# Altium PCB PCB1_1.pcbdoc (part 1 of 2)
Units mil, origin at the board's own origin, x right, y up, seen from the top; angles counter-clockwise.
Board outline 2550 x 2850 mil, 4 copper layers (Top Layer, GND02, PWR03, Bottom Layer), stack 64.1 mil thick; 130 components, 80 nets, 440 pads, 327 vias.
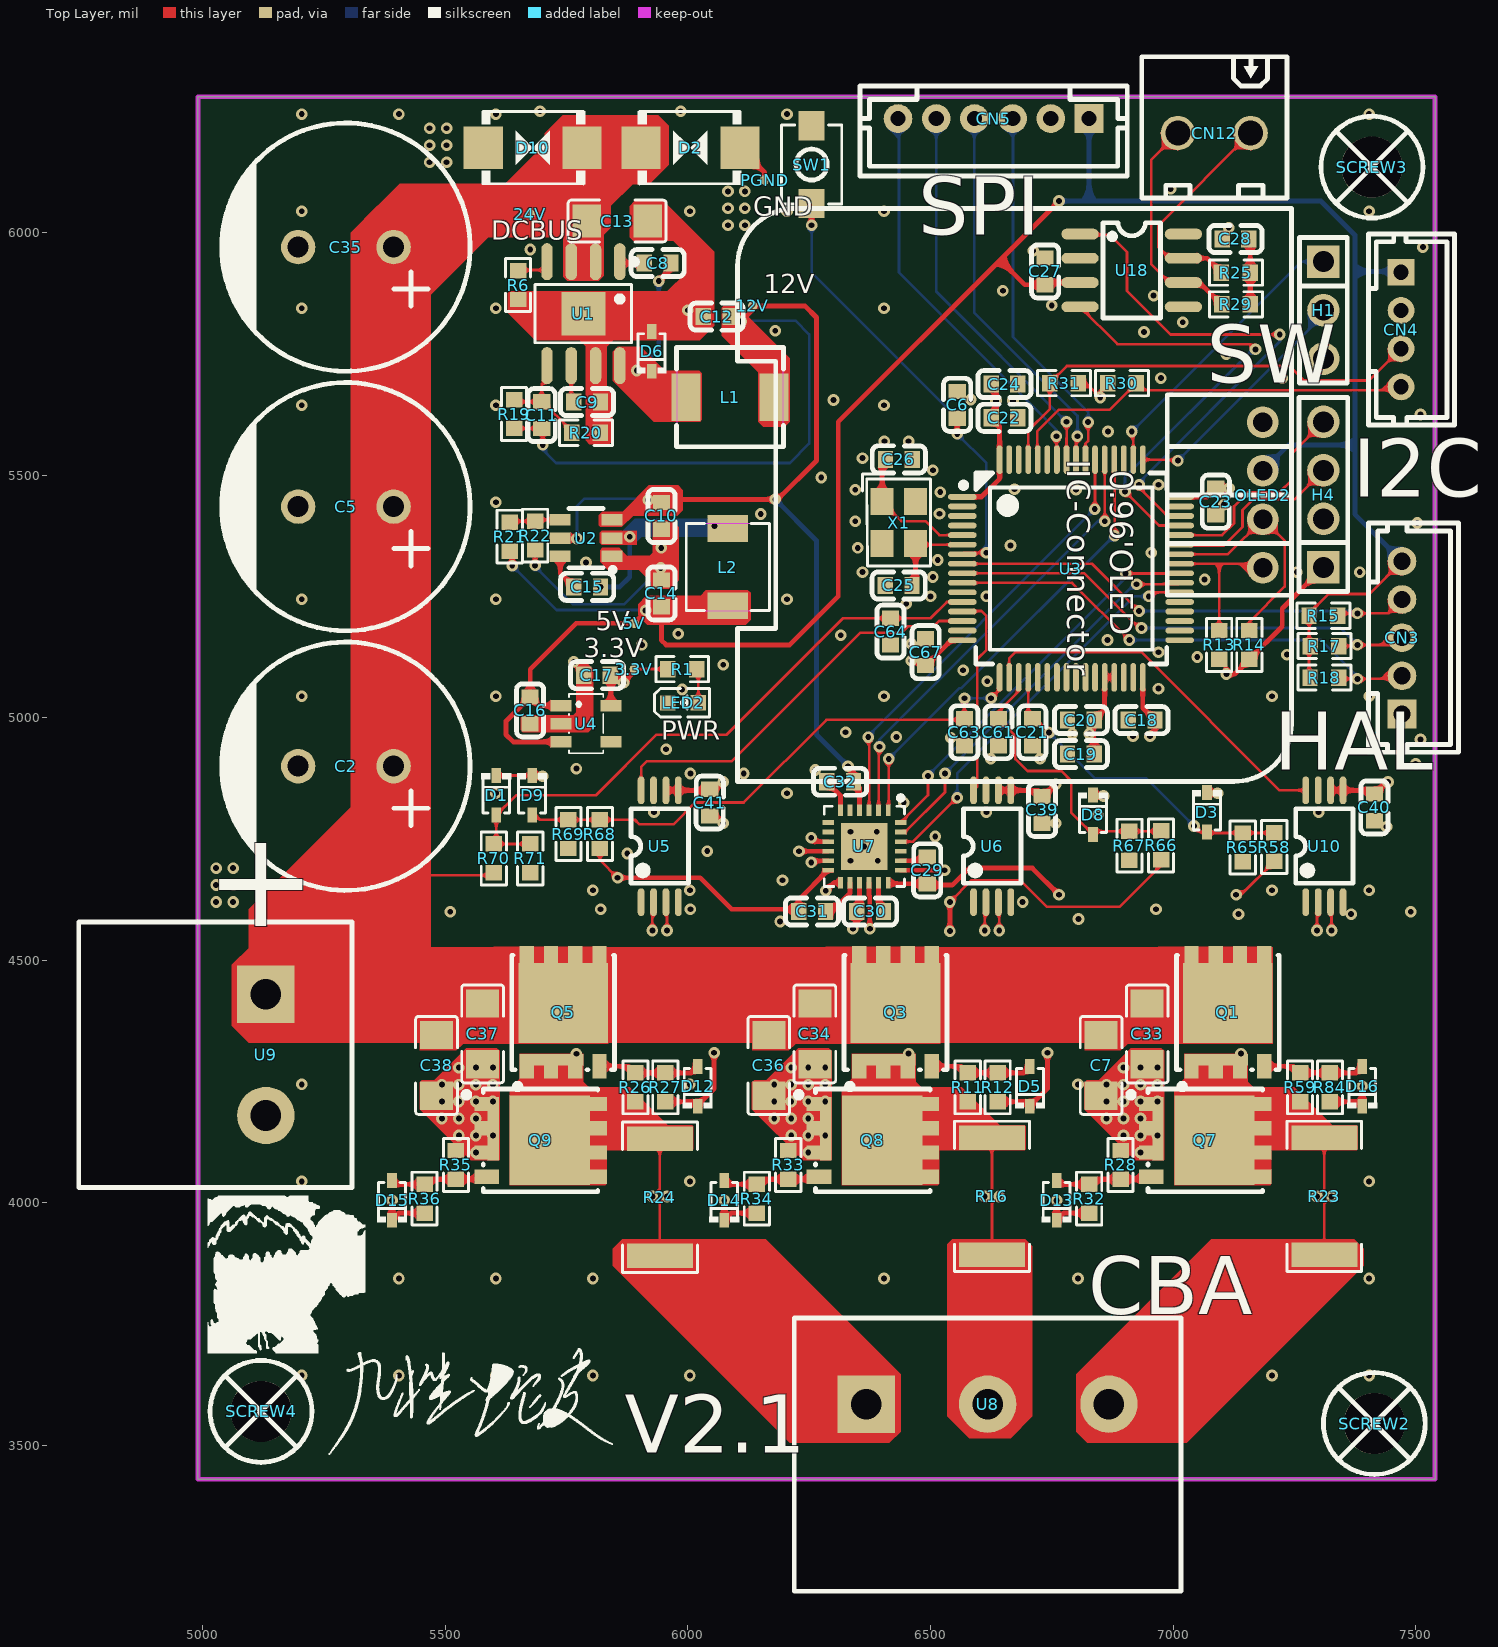
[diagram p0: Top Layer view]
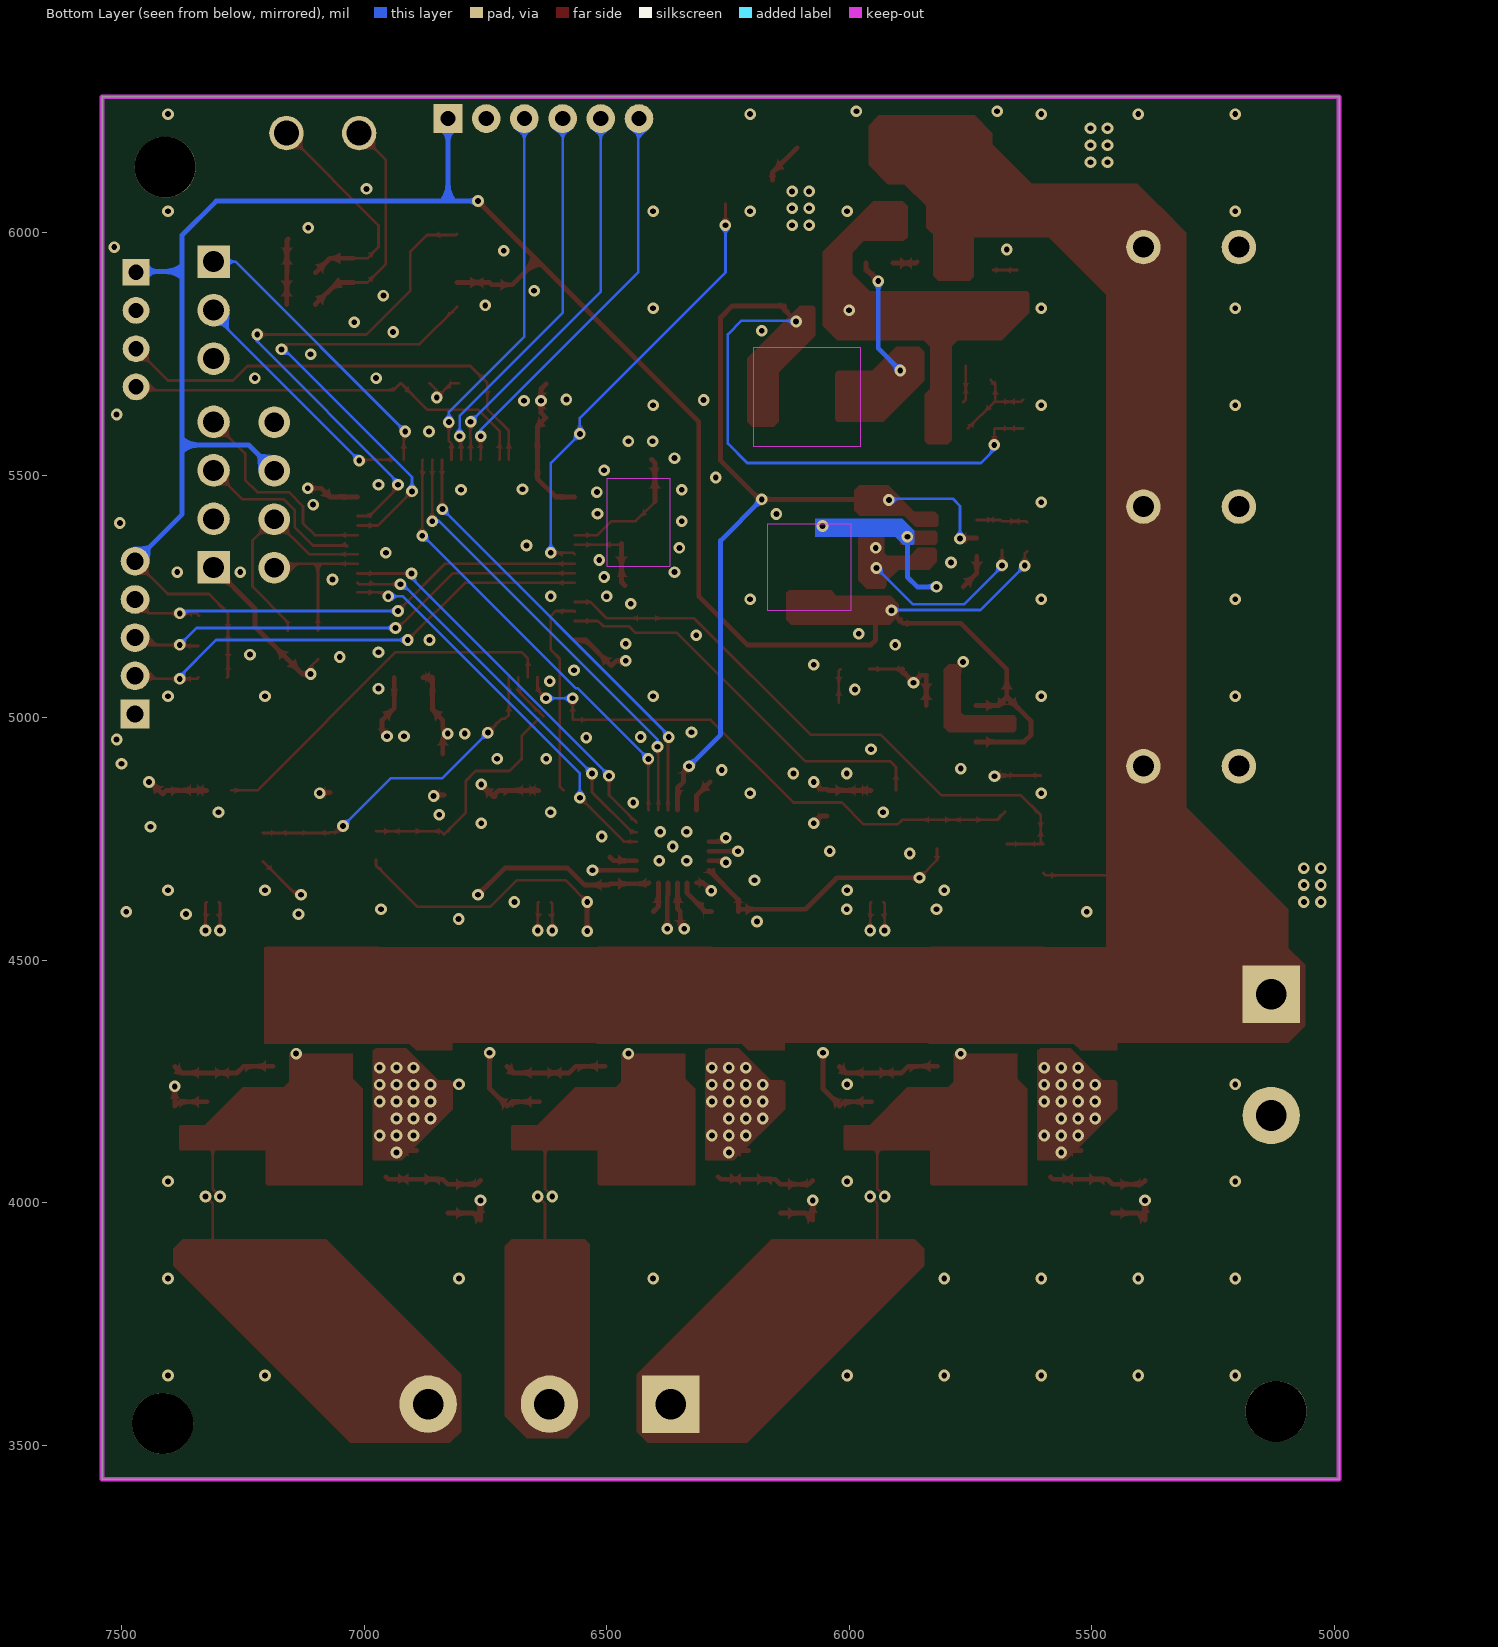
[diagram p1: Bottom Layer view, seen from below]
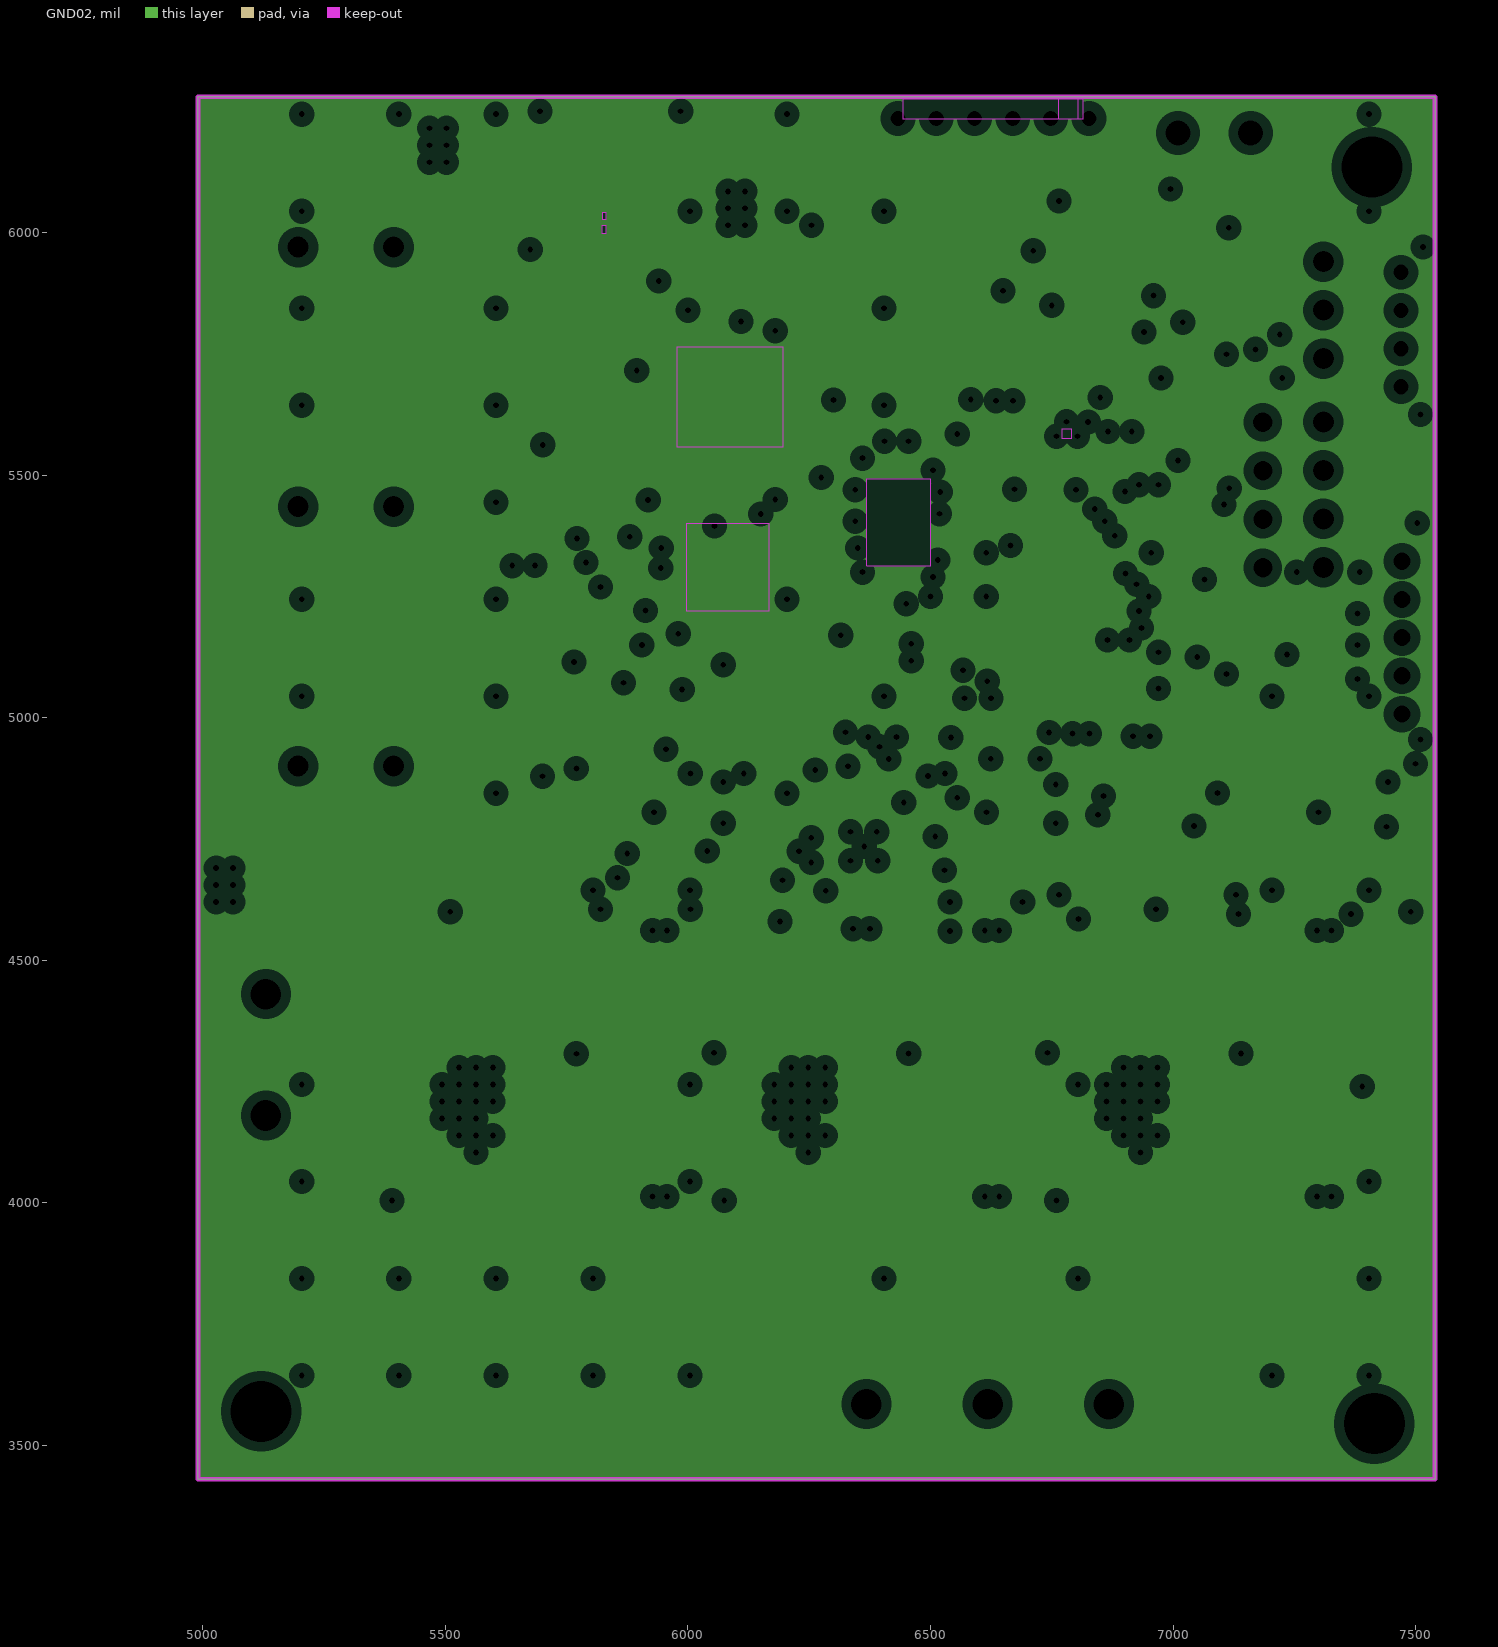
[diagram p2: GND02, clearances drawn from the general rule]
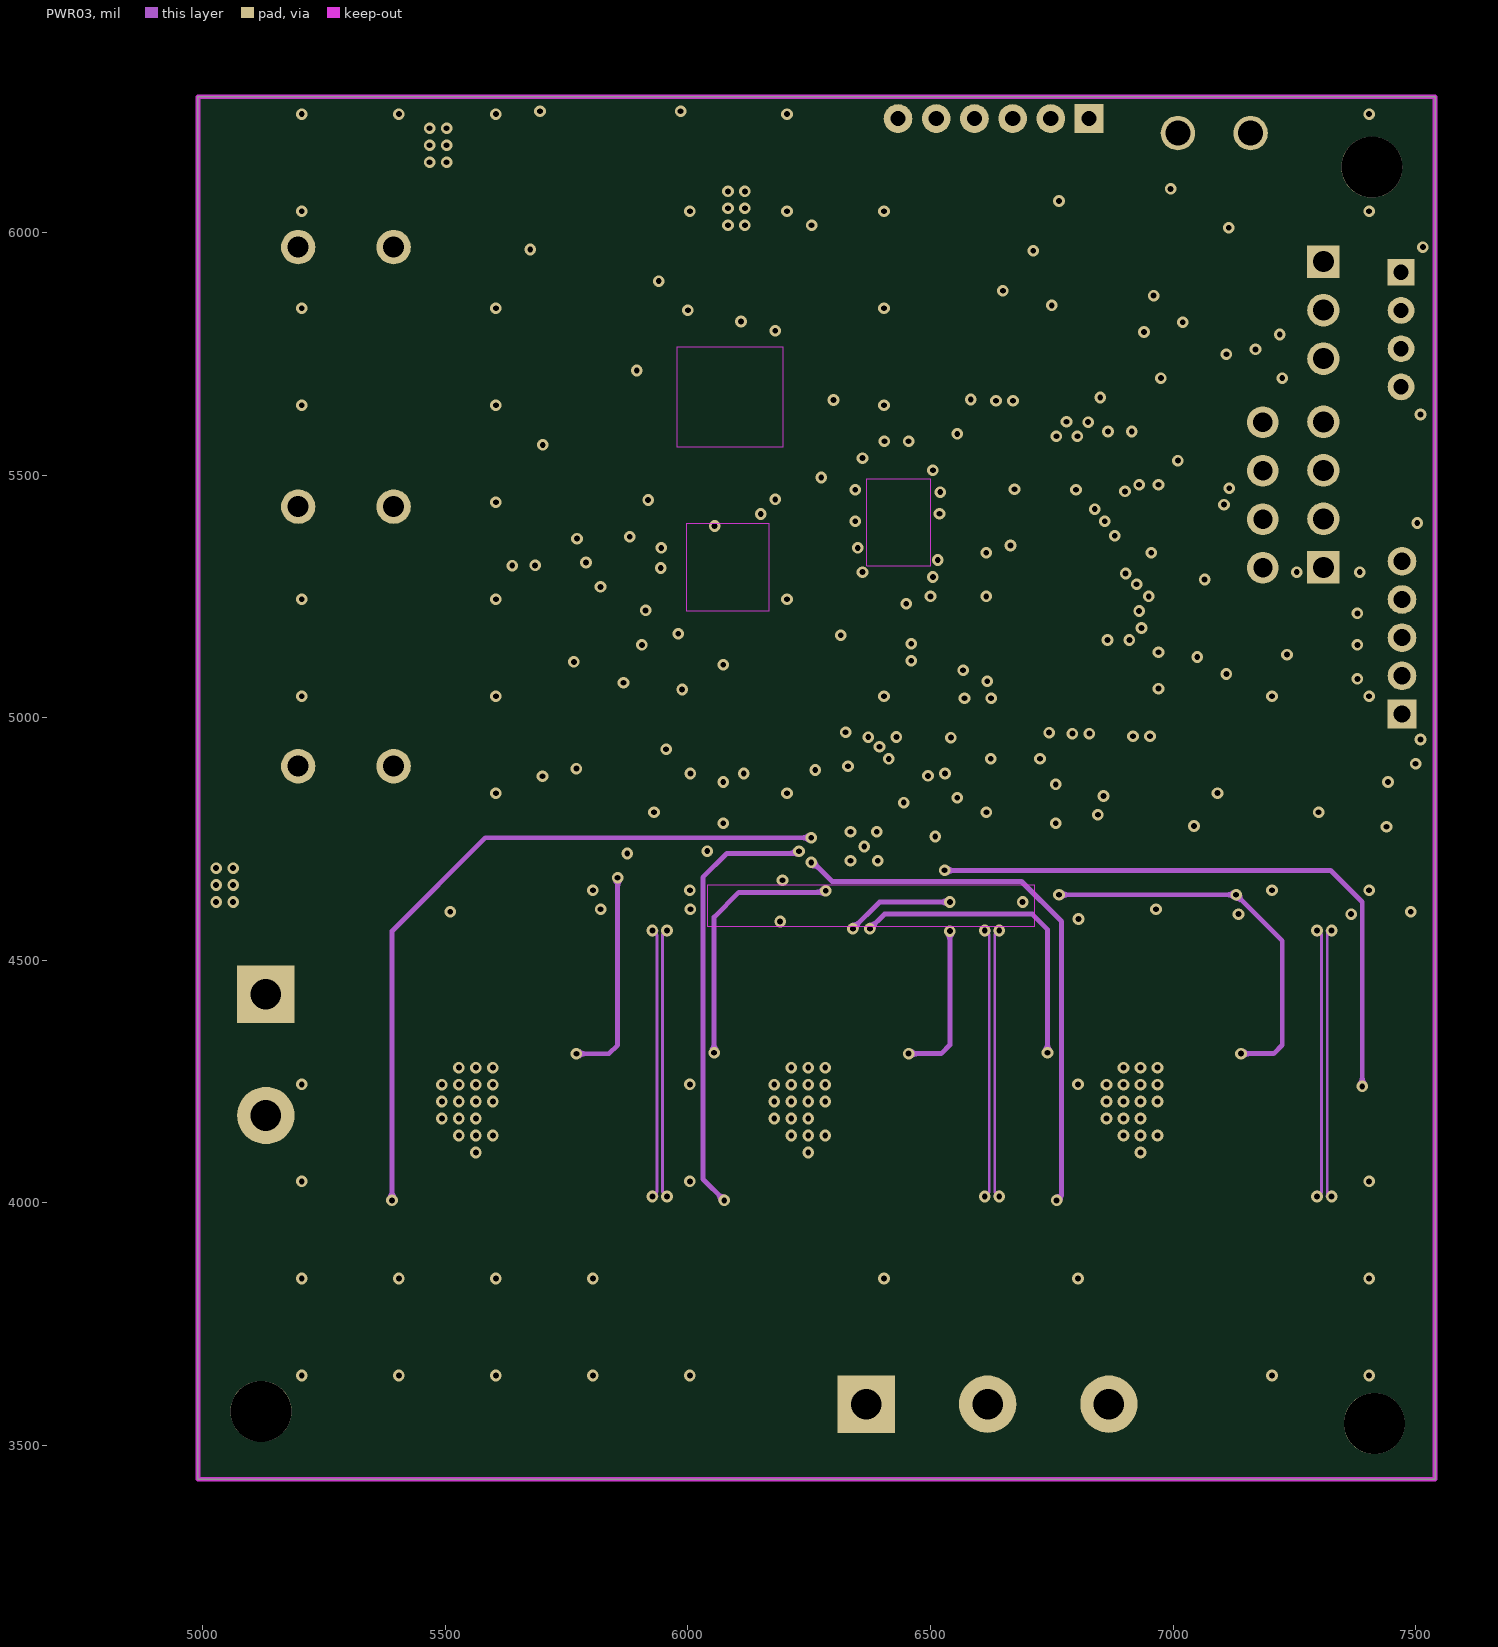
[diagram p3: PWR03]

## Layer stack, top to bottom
Top Layer: signal copper 1.4
Dielectric1: surface 8.3, 7628 RC49% 8.6mil, Dk 0
GND02: plane copper 1.4
Dielectric2: surface 41.9, 1.1mm H/HOZ Copper, Dk 0
PWR03: signal copper 1.4
Dielectric3: surface 8.3, 7628 RC49% 8.6mil, Dk 0
Bottom Layer: signal copper 1.4

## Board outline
4990,6280 4990,3430 7540,3430 7540,6280

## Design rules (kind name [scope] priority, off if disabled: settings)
BoardOutlineClearance copperThickness1oz [All] p0: genericclearance=10 ignorepadtopadclearanceinfootprint=FALSE except(0: Arc-SplitContinuation Track-SplitContinuation SMDPad-SplitContinuation THPad-SplitContinuation Via-SplitContinuation Fill-SplitContinuation Poly-SplitContinuation Region-SplitContinuation Text-SplitContinuation)
BoardOutlineClearance copperThickness2oz [All] p0: genericclearance=10 ignorepadtopadclearanceinfootprint=FALSE except(0: Arc-SplitContinuation Track-SplitContinuation SMDPad-SplitContinuation THPad-SplitContinuation Via-SplitContinuation Fill-SplitContinuation Poly-SplitContinuation Region-SplitContinuation Text-SplitContinuation)
BoardOutlineClearance copperThicknessInner0.5oz [All] p0: genericclearance=10 ignorepadtopadclearanceinfootprint=FALSE except(0: Arc-SplitContinuation Track-SplitContinuation SMDPad-SplitContinuation THPad-SplitContinuation Via-SplitContinuation Fill-SplitContinuation Poly-SplitContinuation Region-SplitContinuation Text-SplitContinuation)
BoardOutlineClearance 3W [All] p0: genericclearance=10 ignorepadtopadclearanceinfootprint=FALSE except(0: Arc-SplitContinuation Track-SplitContinuation SMDPad-SplitContinuation THPad-SplitContinuation Via-SplitContinuation Fill-SplitContinuation Poly-SplitContinuation Region-SplitContinuation Text-SplitContinuation)
BoardOutlineClearance otherClearance [All] p0: genericclearance=10 ignorepadtopadclearanceinfootprint=FALSE except(0: Arc-SplitContinuation Track-SplitContinuation SMDPad-SplitContinuation THPad-SplitContinuation Via-SplitContinuation Fill-SplitContinuation Poly-SplitContinuation Region-SplitContinuation Text-SplitContinuation)
Clearance copperThickness1oz [All] p1: gap=7 ignorepadtopadclearanceinfootprint=FALSE
Clearance copperThickness2oz [All] p1: gap=7 ignorepadtopadclearanceinfootprint=FALSE
Clearance copperThicknessInner0.5oz [All] p1: gap=7 ignorepadtopadclearanceinfootprint=FALSE
Clearance 3W [(InNet('PF1-OSC_OUT') OR InNet('PF0-OSC_IN') OR InNet('ADC_AI') OR InNet('ADC_BI') OR InNet('ADC_CI') OR InNet('ADC_AU') OR InNet('ADC_BU') OR InNet('ADC_CU'))] p1: gap=7 ignorepadtopadclearanceinfootprint=FALSE
Clearance otherClearance [All] p1: gap=7 ignorepadtopadclearanceinfootprint=FALSE
DiffPairsRouting differentialPair [All] p1: maxuncoupledlength=10 minlimit=5.9843 maxlimit=Infinity mostfreqgap=5.9843 toplayer_minwidth=5 toplayer_prefwidth=10 toplayer_maxwidth=100 bottomlayer_minwidth=5 bottomlayer_prefwidth=10 bottomlayer_maxwidth=100 midlayer1_minwidth=5 midlayer1_prefwidth=10 midlayer1_maxwidth=100
PasteMaskExpansion pasteMaskExpansion [All] p1: expansion=0
PlaneConnect innerPlane [All] p1: planeconnectstyle=Relief reliefexpansion=20 reliefentries=4 reliefconductorwidth=10 reliefairgap=10
PlaneConnect 直连 [All] p1: planeconnectstyle=Direct reliefexpansion=20 reliefentries=4 reliefconductorwidth=10 reliefairgap=10
PolygonConnect copperRegion [All] p1: connectstyle=Relief reliefentries=4 reliefconductorwidth=10 polygonreliefangle="90 Angle" airgapwidth=10
PolygonConnect 直连 [All] p1: connectstyle=Direct reliefentries=4 reliefconductorwidth=10 polygonreliefangle="90 Angle" airgapwidth=10
RoutingVias viaSize [All] p1: viastyle="Through Hole" holewidth=12 minholewidth=7.874 maxholewidth=248.0314 width=12 minwidth=7.874 maxwidth=248.0314
RoutingVias 大过孔 [All] p1: viastyle="Through Hole" holewidth=12.0078 minholewidth=11.811 maxholewidth=248.0316 width=12.0078 minwidth=11.811 maxwidth=248.0316
SolderMaskExpansion solderMaskExpansion [IsVia] p1: useseparateexpansions=TRUE expansion=-1000 expansionbottom=-1000
SolderMaskExpansion solderMaskExpansion [All] p2: useseparateexpansions=TRUE expansion=2.0079 expansionbottom=2.0079
Width copperThickness1oz [All] p1: maxlimit=100 minlimit=4 preferedwidth=6
Width copperThickness2oz [All] p1: maxlimit=100 minlimit=8 preferedwidth=10
Width copperThickness0.5oz [All] p1: maxlimit=100 minlimit=4 preferedwidth=10

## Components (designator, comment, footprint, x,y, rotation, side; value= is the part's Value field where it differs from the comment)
3.3V "" Test-Point-0.5mm 5889.7,5100.2 r0 top
5V "" Test-Point-0.5mm 5889.1,5194.6 r0 top
12V "" Test-Point-0.5mm 6133.5,5849 r0 top
24V "" Test-Point-0.5mm 5674.7,6038.2 r0 top
C2 "470uF" CAP-TH_BD13.0-P5.00-D0.6-FD 5295,4900 r180 top
C5 "470uF" CAP-TH_BD13.0-P5.00-D0.6-FD 5295,5435 r180 top
C6 "100nF" C0603#1 6555,5645 r270 top
C7 "4.7uF" C1206 6851.8,4283.1 r270 top
C8 "100nF" C0603#2 5937.6,5937 r0 top
C9 "100nF" C0603#2 5792.1,5650.6 r180 top
C10 "100nF" C0603#1 5945.5,5415.8 r90 top
C11 "100nF" C0603#2 5698.5,5623.7 r270 top
C12 "100nF" C0603#2 6059.3,5826.8 r0 top
C13 "100nF" C1206 5854.1,6023.8 r180 top
C14 "100nF" C0603#3 5945.3,5256.2 r270 top
C15 "100nF" C0603#2 5792.2,5269.6 r0 top
C16 "100nF" C0603#3 5674.6,5015.1 r90 top
C17 "100nF" C0603#3 5812.6,5087.6 r0 top
C18 "100nF" C0603#1 6935,4995 r180 top
C19 "100nF" C0603#1 6810,4925 r180 top
C20 "100nF" C0603#1 6810,4995 r0 top
C21 "100nF" C0603#1 6710,4970 r90 top
C22 "100nF" C0603#2 6652.6,5618.2 r180 top
C23 "100nF" C0603#3 7088.1,5445.4 r90 top
C24 "100nF" C0603#2 6652.6,5687.7 r180 top
C25 "100nF" C0603#2 6434.5,5272.5 r0 top
C26 "100nF" C0603#3 6434.8,5532.5 r0 top
C27 "100nF" C0603#2 6736.3,5920 r270 top
C28 "100nF" C0603#3 7128.8,5986.8 r0 top
C29 "100nF" C0603#2 6493.3,4685.3 r90 top
C30 "100nF" C0603#2 6375.7,4600.5 r180 top
C31 "100nF" C0603#2 6255.9,4600.5 r180 top
C32 "100nF" C0603#2 6313.7,4868 r0 top
C33 "4.7uF" C1206 6946.8,4348.1 r270 top
C34 "4.7uF" C1206 6261.8,4348.1 r270 top
C35 "470uF" CAP-TH_BD13.0-P5.00-D0.6-FD 5295,5970 r180 top
C36 "4.7uF" C1206 6166.8,4283.1 r270 top
C37 "4.7uF" C1206 5576.8,4348.1 r270 top
C38 "4.7uF" C1206 5481.8,4283.1 r270 top
C39 "100nF" C0603#1 6730,4810 r90 top
C40 "100nF" C0603#1 7415,4815 r90 top
C41 "100nF" C0603#1 6045,4825 r90 top
C61 "100nF" C0603#1 6640,4970 r90 top
C63 "100nF" C0603#1 6570,4970 r90 top
C64 "100nF" C0603#2 6417.6,5177.4 r90 top
C67 "100nF" C0603#1 6490,5135 r270 top
CN3 "LAIL-PHC2.0-5P-01-PH-L" CONN-TH_5P-P2.00_ZX-PH2.0-5PZZ 7472,5165 r90 top
CN4 "LAIL-PHC2.0-4P-01-PH-L" CONN-TH_HC-PH-4A-Y-K-10 7470,5800 r270 top
CN5 "LAIL-PHC2.0-6P-01-PH-L" CONN-TH_6P-P2.00_LAIL-PHC2.0-6P-01-PH-L 6630,6235 r180 top
CN12 "MX128L-3.81-02P-GN01-Cu-Y-A" CONN-TH_2P-P3.81_MX128L-3.81-GN01-02P-CU-Y-A 7085,6205 r180 top
D1 "B16WS" SOD-323_L1.7-W1.3-LS2.5-FD#1 5605,4840 r90 top
D2 "SMBJ28CA" SMB_L4.6-W3.6-LS5.4-BI 6005,6175 r180 top
D3 "B16WS" SOD-323_L1.7-W1.3-LS2.5-FD#1 7070,4805 r90 top
D5 "B16WS" SOD-323_L1.7-W1.3-LS2.5-FD#1 6705,4240 r270 top
D6 "B16WS" SOD-323_L1.7-W1.3-LS2.5-FD#1 5925,5755 r270 top
D8 "B16WS" SOD-323_L1.7-W1.3-LS2.5-FD#1 6835,4800 r90 top
D9 "B16WS" SOD-323_L1.7-W1.3-LS2.5-FD#2 5678.7,4840 r90 top
D10 "SMBJ28CA" SMB_L4.6-W3.6-LS5.4-BI 5680,6175 r0 top
D12 "B16WS" SOD-323_L1.7-W1.3-LS2.5-FD#1 6020,4240 r270 top
D13 "B16WS" SOD-323_L1.7-W1.3-LS2.5-FD#1 6760,4005 r270 top
D14 "B16WS" SOD-323_L1.7-W1.3-LS2.5-FD#1 6075,4005 r270 top
D15 "B16WS" SOD-323_L1.7-W1.3-LS2.5-FD#1 5390,4005 r270 top
D16 "B16WS" SOD-323_L1.7-W1.3-LS2.5-FD#1 7390,4240 r270 top
H1 "" HDR-TH_3P-P2.54-V-M 7310,5840 r270 top
H4 "" HDR-TH_4P-P2.54-V-M 7310,5460 r90 top
L1 "22uH" IND-SMD_L5.5-W5.2 6086.8,5660.8 r0 top
L2 "10uH" IND-SMD_L4.4-W4.2 6082.2,5310.3 r90 top
LED2 "" LED_0603 5992,5030.8 r0 top
OLED2 "0.96OLED_4P_MODULE_JX" 0.96OLED_4P 7185,5459 r270 top
PGND "" Test-Point-0.5mm 6157.9,6108.3 r0 top
Q1 "BSC007N04LS6" PG-TDSON-8-FL_L5.0-W6.0-P1.27-LS6.2-BL 7112.9,4392.4 r0 top
Q3 "BSC007N04LS6" PG-TDSON-8-FL_L5.0-W6.0-P1.27-LS6.2-BL 6427.9,4392.4 r0 top
Q5 "BSC007N04LS6" PG-TDSON-8-FL_L5.0-W6.0-P1.27-LS6.2-BL 5742.9,4392.4 r0 top
Q7 "BSC007N04LS6" PG-TDSON-8-FL_L5.0-W6.0-P1.27-LS6.2-BL 7066.2,4128.7 r270 top
Q8 "BSC007N04LS6" PG-TDSON-8-FL_L5.0-W6.0-P1.27-LS6.2-BL 6381.2,4128.7 r270 top
Q9 "BSC007N04LS6" PG-TDSON-8-FL_L5.0-W6.0-P1.27-LS6.2-BL 5696.2,4128.7 r270 top
R1 "10K" R0603#1 5988.3,5100 r180 top
R6 "10K" R0603#2 5649.9,5891.7 r90 top
R11 "10K" R0603#2 6576.8,4238.1 r90 top
R12 "10K" R0603#2 6638.5,4238.1 r90 top
R13 "10K" R0603#2 7095,5150 r270 top
R14 "10K" R0603#2 7157.4,5150 r270 top
R15 "10K" R0603#2 7310,5210 r180 top
R16 "0.5mΩ" R2512 6626.8,4013.1 r270 top
R17 "10K" R0603#1 7312.2,5147.7 r180 top
R18 "10K" R0603#3 7311.9,5082.7 r180 top
R19 "10K" R0603#1 5641.6,5625.9 r270 top
R20 "10K" R0603#1 5789.9,5587.4 r180 top
R21 "10K" R0603#1 5632.8,5373.1 r270 top
R22 "10K" R0603#1 5685,5375.2 r90 top
R23 "0.5mΩ" R2512 7311.8,4013.1 r270 top
R24 "0.5mΩ" R2512 5942.4,4011.7 r270 top
R25 "10K" R0603#3 7129.4,5917.4 r180 top
R26 "10K" R0603#2 5891.8,4238.1 r90 top
R27 "10K" R0603#2 5953.5,4238.1 r90 top
R28 "10K" R0603#2 6891.8,4078.1 r270 top
R29 "10K" R0603#3 7129.8,5852 r0 top
R30 "10K" R0603#1 6894.7,5689.7 r180 top
R31 "10K" R0603#1 6775.3,5689.7 r0 top
R32 "10K" R0603#1 6827.1,4008.4 r90 top
R33 "10K" R0603#2 6206.8,4078.1 r270 top
R34 "10K" R0603#1 6142.1,4008.4 r90 top
R35 "10K" R0603#2 5521.8,4078.1 r270 top
R36 "10K" R0603#1 5457.1,4008.4 r90 top
R58 "10K" R0603#1 7208.7,4733.4 r270 top
R59 "10K" R0603#2 7261.8,4238.1 r90 top
R65 "10K" R0603#3 7143.7,4732.7 r90 top
R66 "10K" R0603#2 6975.2,4736.8 r270 top
R67 "10K" R0603#1 6910.2,4736.1 r90 top
R68 "10K" R0603#1 5818.7,4760 r270 top
R69 "10K" R0603#3 5753.7,4760 r90 top
R70 "10K" R0603#2 5600,4710 r270 top
R71 "10K" R0603#2 5675,4710 r90 top
R84 "10K" R0603#2 7323.5,4238.1 r90 top
SCREW2 "" M3螺丝 7415,3545 r0 top
SCREW3 "" M3螺丝 7410,6135 r0 top
SCREW4 "" M3螺丝 5120,3570 r0 top
SW1 "" Key_SMD_3x4x2 6255,6140.2 r270 top
U1 "LMR16030SDDAR" SOIC-8_L4.9-W3.9-P1.27-LS6.0-BL-EP2.3 5784.5,5832.8 r180 top
U2 "TPS562201DDCR" SOT-23-6_L2.9-W1.6-P0.95-LS2.8-BR 5790,5370.2 r0 top
U3 "STM32G431RBT6" LQFP-64_L10.0-W10.0-P0.50-LS12.0-BL 6789.6,5307.5 r270 top
U4 "LP5907MFX-3.3/NOPB" SOT-23-5_L3.0-W1.7-P0.95-LS2.8-BR 5789.9,4987.6 r180 top
U5 "INA240A1PWR" TSSOP-8_L4.4-W3.0-P0.65-LS6.4-BL 5941.9,4735 r0 top
U6 "INA240A1PWR" TSSOP-8_L4.4-W3.0-P0.65-LS6.4-BL 6627.2,4735 r0 top
U7 "DRV8300DRGER" VQFN-24_L4.0-W4.0-P0.50-TL-EP2.5 6363.6,4734.6 r270 top
U8 "HB611-6.35-3P" CONN-TH_HB611-6.35-3P 6617.8,3585 r0 top
U9 "HB611-6.35-2P" CONN-TH_HB611-6.35-2P 5130,4305 r270 top
U10 "INA240A1PWR" TSSOP-8_L4.4-W3.0-P0.65-LS6.4-BL 7312,4735 r0 top
U18 "TJA1050T/CM,118" SOIC-8_L5.0-W4.0-P1.27-LS6.0-BL 6914.8,5922 r270 top
X1 "8MHz" CRYSTAL-SMD_4P-L3.2-W2.5-BL-1 6434.8,5402.3 r270 top

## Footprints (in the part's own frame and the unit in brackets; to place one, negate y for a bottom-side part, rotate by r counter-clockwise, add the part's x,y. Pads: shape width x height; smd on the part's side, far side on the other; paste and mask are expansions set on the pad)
0.96OLED_4P [mil]
  round 65 hole 39.4: 1(-150,0) 2(-50,0.1) 3(50,0.1) 4(150,0.1)
  silkscreen extent -591,-1083 591,59
C0603#1 [mil]
  rect 31.5x35.4 smd: 1(-27.6,0) 2(27.6,0)
  silkscreen extent -55,-28 55,28
C0603#2 [mil]
  rect 31.5x35.4 smd: 1(-27.5,0) 2(27.6,0)
  silkscreen extent -55,-28 55,28
C0603#3 [mil]
  rect 31.5x35.4 smd: 1(-27.6,0) 2(27.5,0)
  silkscreen extent -55,-28 55,28
C1206 [mil]
  rect 58.5x68 smd paste-3937 mask+2: 1(-62.7,0) 2(62.7,0)
  silkscreen extent -101,-43 101,43
CAP-TH_BD13.0-P5.00-D0.6-FD [mil]
  round 70.9 hole 43.3: 1(-98.4,0) 2(98.4,0)
  silkscreen extent -256,-256 256,256
CONN-TH_2P-P3.81_MX128L-3.81-GN01-02P-CU-Y-A [mil]
  round 70.9 hole 51.2 paste+0 mask+2: 1(-75,0) 2(75,0)
  silkscreen extent -150,-158 150,134
CONN-TH_5P-P2.00_ZX-PH2.0-5PZZ [mil]
  rect 59.1x59.1 hole 35.4 paste+0 mask+2: 1(-157.5,0)
  round 59.1 hole 35.4 paste+0 mask+2: 2(-78.7,0) 3(0,0) 4(78.7,0) 5(157.5,0)
  silkscreen extent -236,-116 236,69
CONN-TH_6P-P2.00_LAIL-PHC2.0-6P-01-PH-L [mil]
  rect 59.1x59.1 hole 31.5 paste+0 mask+2: 1(-196.9,0)
  round 59.1 hole 31.5 paste+0 mask+2: 2(-118.1,0) 3(-39.4,0) 4(39.4,0) 5(118.1,0) 6(196.9,0)
  silkscreen extent -276,-67 276,118
CONN-TH_HB611-6.35-2P [mil]
  rect 118.1x118.1 hole 63: 1(-125,0)
  round 118.1 hole 63: 2(125,0)
  silkscreen extent -274,-386 274,177
CONN-TH_HB611-6.35-3P [mil]
  rect 118.1x118.1 hole 63: 1(-250,0)
  round 118.1 hole 63: 2(0,0) 3(250,0)
  silkscreen extent -399,-386 399,177
CONN-TH_HC-PH-4A-Y-K-10 [mil]
  rect 55.1x55.1 hole 31.5: 1(-118.1,0)
  round 55.1 hole 31.5: 2(-39.4,0) 3(39.4,0) 4(118.1,0)
  silkscreen extent -197,-67 197,110
CRYSTAL-SMD_4P-L3.2-W2.5-BL-1 [mil]
  rect 55.1x47.2 smd: 1(-43.3,-34.4) 2(43.3,-34.4) 3(43.3,34.5) 4(-43.3,34.5)
  silkscreen extent -100,-75 90,65
HDR-TH_3P-P2.54-V-M [mil]
  rect 66.9x66.9 hole 43.3: 1(-100,0)
  round 66.9 hole 43.3: 2(0,0) 3(100,0)
  silkscreen extent -150,-49 150,49
HDR-TH_4P-P2.54-V-M [mil]
  rect 66.9x66.9 hole 43.3: 1(-150,0)
  round 66.9 hole 43.3: 2(-50,0) 3(50,0) 4(150,0)
  silkscreen extent -200,-50 200,50
IND-SMD_L4.4-W4.2 [mil]
  rect 55.1x83.5 smd: 1(79.9,0) 2(-79.8,0)
  silkscreen extent -90,-86 90,86
IND-SMD_L5.5-W5.2 [mil]
  rect 59.1x98.4 smd: 1(-90.6,0) 2(90.5,0)
  silkscreen extent -110,-102 110,102
Key_SMD_3x4x2 [mil]
  rect 60.2x53.5 smd paste+0 mask+2: 1(-80.2,0) 2(80.1,0)
  silkscreen extent -82,-62 82,62
LED_0603 [mil]
  rect 31.5x31.5 smd paste+0 mask+2: 1(-33.5,-0.4) 2(29.5,-0.2)
  silkscreen extent -61,-30 53,30
LQFP-64_L10.0-W10.0-P0.50-LS12.0-BL [mil]
  oval 11.8x59.1 smd: 1(-147.6,-223.9) 2(-128,-223.9) 3(-108.3,-223.9) 4(-88.6,-223.9) 5(-68.9,-223.9) 6(-49.2,-223.9) 7(-29.5,-223.9) 8(-9.8,-223.9) 9(9.8,-223.9) 10(29.5,-223.9) 11(49.2,-223.9) 12(68.9,-223.9) 13(88.6,-223.9) 14(108.3,-223.9) 15(127.9,-223.9) 16(147.6,-223.9) 33(147.6,224) 34(127.9,224) 35(108.3,224) 36(88.6,224) 37(68.9,224) 38(49.2,224) 39(29.5,224) 40(9.8,224) 41(-9.8,224) 42(-29.5,224) 43(-49.2,224) 44(-68.9,224) 45(-88.6,224) 46(-108.3,224) 47(-128,224) 48(-147.6,224)
  oval 59.1x11.8 smd: 17(224.4,-147.1) 18(224.4,-127.4) 19(224.4,-107.8) 20(224.4,-88.1) 21(224.4,-68.4) 22(224.4,-48.7) 23(224.4,-29) 24(224.4,-9.3) 25(224.4,10.3) 26(224.4,30) 27(224.4,49.7) 28(224.4,69.4) 29(224.4,89.1) 30(224.4,108.8) 31(224.4,128.5) 32(224.4,148.1) 49(-224.4,148.1) 50(-224.4,128.5) 51(-224.4,108.8) 52(-224.4,89.1) 53(-224.4,69.4) 54(-224.4,49.7) 55(-224.4,30) 56(-224.4,10.3) 57(-224.4,-9.3) 58(-224.4,-29) 59(-224.4,-48.7) 60(-224.4,-68.4) 61(-224.4,-88.1) 62(-224.4,-107.8) 63(-224.4,-127.4) 64(-224.4,-147.1)
  silkscreen extent -197,-227 197,197
M3螺丝 [mil]
  round 126 hole 126 paste+0 mask+4: 1(0,0)
  silkscreen extent -105,-105 105,105
PG-TDSON-8-FL_L5.0-W6.0-P1.27-LS6.2-BL [mil]
  rect 29.5x51.2 smd paste-3937 mask+2: 1(-75,-111) 2(-25,-111) 3(25,-111) 4(75,-111) 5(75,111) 6(25,111) 7(-25,111) 8(-75,111)
  rect 129.9x23.6 smd paste-3937 mask+2: 3(-23.6,-97.2)
  rect 185x165.4 smd paste-3937 mask+2: 8(0,19.2)
  silkscreen extent -106,-159 106,118
R0603#1 [mil]
  rect 31.8x34 smd paste-3937 mask+2: 1(-29.6,0) 2(29.7,0)
  silkscreen extent -54,-26 54,26
R0603#2 [mil]
  rect 31.8x34 smd paste-3937 mask+2: 1(-29.7,0) 2(29.7,0)
  silkscreen extent -54,-26 54,26
R0603#3 [mil]
  rect 31.8x34 smd paste-3937 mask+2: 1(-29.7,0) 2(29.6,0)
  silkscreen extent -55,-26 54,26
R2512 [mil]
  rect 50.5x136.1 smd paste-3937 mask+2: 1(-120.7,0) 2(120.7,0)
  silkscreen extent -155,-77 155,77
SMB_L4.6-W3.6-LS5.4-BI [mil]
  rect 80.6x88.2 smd: 1(-102,0) 2(102,0)
  silkscreen extent -105,-75 108,75
SOD-323_L1.7-W1.3-LS2.5-FD#1 [mil]
  rect 30.7x19.7 smd: 1(-40.9,0) 2(40.9,0)
  silkscreen extent -36,-31 46,31
SOD-323_L1.7-W1.3-LS2.5-FD#2 [mil]
  rect 30.7x19.7 smd: 1(-41,0) 2(40.9,0)
  silkscreen extent -36,-31 45,31
SOIC-8_L4.9-W3.9-P1.27-LS6.0-BL-EP2.3 [mil]
  oval 23.7x76.4 smd paste+0 mask+2: 1(-75,-107.2) 2(-25,-107.2) 3(25,-107.2) 4(75,-107.2) 5(75,107.1) 6(25,107.1) 7(-25,107.1) 8(-75,107.1)
  rect 90.2x90.2 smd paste+0 mask+2: 9(0,0)
  silkscreen extent -111,-113 100,60
SOIC-8_L5.0-W4.0-P1.27-LS6.0-BL [mil]
  oval 22.4x76.8 smd: 1(-75,-106.5) 2(-25,-106.5) 3(25,-106.5) 4(75,-106.5) 5(75,106.5) 6(25,106.5) 7(-25,106.5) 8(-75,106.5)
  silkscreen extent -98,-59 98,59
SOT-23-5_L3.0-W1.7-P0.95-LS2.8-BR [mil]
  rect 43.3x23.6 smd: 1(51.1,-37.4) 2(51.1,0) 3(51.1,37.4) 4(-51.2,37.4) 5(-51.2,-37.4)
  silkscreen extent -36,-61 35,61
SOT-23-6_L2.9-W1.6-P0.95-LS2.8-BR [mil]
  rect 43.3x23.6 smd paste+0 mask+2: 1(53.1,-37.4) 2(53.1,0) 3(53.1,37.4) 4(-53.2,37.4) 5(-53.2,0) 6(-53.2,-37.4)
  silkscreen extent -36,-70 60,61
Test-Point-0.5mm [mil]
  round 19.7 smd: 1(0,0)
TSSOP-8_L4.4-W3.0-P0.65-LS6.4-BL [mil]
  oval 13.9x57.2 smd: 1(-38.4,-115.2) 2(-12.8,-115.2) 3(12.8,-115.2) 4(38.4,-115.2) 5(38.4,115.2) 6(12.8,115.2) 7(-12.8,115.2) 8(-38.4,115.2)
  silkscreen extent -59,-76 59,77
VQFN-24_L4.0-W4.0-P0.50-TL-EP2.5 [mil]
  rect 23.6x9.8 smd paste-3937 mask+2: 1(-74.8,49.2) 2(-74.8,29.5) 3(-74.8,9.9) 4(-74.8,-9.8) 5(-74.8,-29.5) 6(-74.8,-49.2) 13(74.8,-49.2) 14(74.8,-29.5) 15(74.8,-9.8) 16(74.8,9.9) 17(74.8,29.5) 18(74.8,49.2)
  rect 9.8x23.6 smd paste-3937 mask+2: 7(-49.2,-74.8) 8(-29.5,-74.8) 9(-9.8,-74.8) 10(9.8,-74.8) 11(29.5,-74.8) 12(49.2,-74.8) 19(49.2,74.8) 20(29.5,74.8) 21(9.8,74.8) 22(-9.8,74.8) 23(-29.5,74.8) 24(-49.2,74.8)
  rect 96.5x96.5 smd paste-3937 mask+2: 25(0,0)
  silkscreen extent -105,-83 83,83

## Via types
v1: diameter 24, hole 12, Top Layer to Bottom Layer, 327 vias

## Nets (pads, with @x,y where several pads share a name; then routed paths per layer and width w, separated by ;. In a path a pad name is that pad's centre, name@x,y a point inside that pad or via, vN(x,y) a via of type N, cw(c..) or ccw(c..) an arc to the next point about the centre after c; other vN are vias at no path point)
3.3V: 3.3V.1 C17.2 C18.1 C19.1 C20.2 C22.2 C23.2 C24.2 C39.2 C40.2 C41.2 C67.2 D1.2 D3.2 D8.2 D9.2 H4.1 R1.2 R13.2 R14.2 R30.2 R31.2 U3.1 U3.16 U3.28 U3.29 U3.32 U3.48 U3.64 U4.5 U5.5 U5.6 U6.5 U6.6 U10.5 U10.6 | length 2050.2
  Top Layer w5.5: D1.2@5605,4880.9 D9.2@5678.7,4880.9 ; 3.3V.1@5889.7,5100.2 5958.4,5100.2 R1.2@5958.6,5100 ; R31.2@6805,5689.7 6820.3,5689.7 v1(6850,5660) 6850,5674.7 R30.2@6865,5689.7 ; R13.2@7095,5120.3 7110,5105.3 v1(7110,5090)
  Top Layer w10: D9.2@5678.7,4880.9 5698.9,4880.9 v1(5700.3,4879.4) ; U4.5@5841.1,5025 5841.1,5086.7 C17.2@5840.1,5087.6 5851.5,5087.6 v1(5867.3,5071.9) 5889.7,5094.3 3.3V.1@5889.7,5100.2 ; U5.6@5954.7,4850.2 U5.5@5980.3,4850.2 6042.7,4850.2 C41.2@6045,4852.6 6058,4852.6 v1(6073,4867.5) ; v1(6460.5,5117.5) 6479.9,5117.5 C67.2@6490,5107.4 6542.4,5159.9 U3.16@6565.7,5159.9 ; U3.1@6565.7,5455.1 6605.1,5455.1 6642.5,5492.5 U3.64@6642.5,5531.9 6642.5,5600.7 C22.2@6625,5618.2 6635.1,5628.2 v1(6635.1,5653.5) 6635.1,5677.6 C24.2@6625,5687.7 ; U6.6@6640,4850.2 U6.5@6665.6,4850.2 6722.3,4850.2 C39.2@6730,4842.6 ; C39.2@6730,4837.6 6733.3,4837.6 v1(6758.2,4862.5) ; D8.2@6835,4840.9 6854.2,4840.9 v1(6856.6,4838.5) ; C19.1@6837.6,4925 6837.6,4957 v1(6827.5,4967.1) 6837.6,4977.1 C20.2@6837.6,4995 6859,5016.4 U3.28@6859,5083.1 U3.29@6878.7,5083.1 ; U3.32@6937.7,5083.1 6937.7,5019.8 C18.1@6962.6,4995 6962.6,4972 v1(6952.5,4961.9) ; U3.48@7013.6,5455.1 7070.3,5455.1 C23.2@7088.1,5472.9 v1(7116,5472.9) ; D3.2@7070,4845.9 7090.1,4845.9 v1(7091.6,4844.5) ; v1(7110,5090) 7127.1,5090 R14.2@7157.4,5120.3 7225,5187.9 7225,5225 H4.1@7310,5310 ; U10.6@7324.8,4850.2 U10.5@7350.4,4850.2 7407.3,4850.2 C40.2@7415,4842.6 7440,4867.5 v1(7443.1,4867.5)
5V: 5V.1 C14.2 C16.2 C27.2 CN3.5 CN4.1 CN5.1 L2.2 OLED2.2 R15.2 R17.2 R18.2 R21.2 U4.1 U4.3 U18.3 | length 4849.8
  Top Layer w5.5: R21.2@5632.8,5343.4 5637.8,5338.4 v1(5637.8,5313.4) ; R18.2@7282.3,5082.7 7280.3,5084.6 R15.2@7280.3,5210 7280.3,5215.3 7320,5255 7404.5,5255 CN3.5@7472,5322.5
  Top Layer w10: U4.3@5738.8,4950.2 5639.8,4950.2 5625,4965 5625,4993 C16.2@5674.6,5042.6 ; U4.1@5738.8,5025 5692.2,5025 C16.2@5674.6,5042.6 ; v1(5912.8,5221.2) 5912.8,5218.3 5V.1@5889.1,5194.6 5769.6,5194.6 5675,5100 5675,5043 C16.2@5674.6,5042.6 ; C14.2@5945.3,5228.7 5945.3,5159.7 5955,5150 6210,5150 6310,5250 6310,5610 6643.5,5943.5 ; v1(6765,6065) 6643.5,5943.5 ; U18.3@6808.3,5897 6740.9,5897 C27.2@6736.3,5892.4 6694.6,5892.4 6643.5,5943.5
  Bottom Layer w5.5: v1(5637.8,5313.4) 5729.2,5222 v1@5911.2,5222
  Bottom Layer w10: v1(6765,6065) 6826.5,6065 ; CN5.1@6826.9,6235 6826.9,6065.4 6826.5,6065 ; OLED2.2@7185.1,5509 7238.2,5562.2 7375,5562.2 ; CN4.1@7470,5918.1 7468.3,5919.9 7375,5919.9 ; CN3.5@7472,5322.5 7375,5419.4 7375,5562.2 ; 6826.5,6065 7305,6065 7375,5995 7375,5919.9 ; 7375,5562.2 7375,5919.9
12V: 12V.1 C10.2 C11.2 C12.2 C32.2 L1.2 R19.2 U2.3 U2.5 U7.4 | length 2854
  Top Layer w5.5: R19.2@5641.6,5596.2 5641.7,5596.1 C11.2@5698.5,5596.1 5700.7,5593.9 v1(5700.7,5562.4)
  Top Layer w10: U2.5@5736.8,5370.2 5770.4,5370.2 v1(5771.4,5369.2) ; C10.2@5945.5,5443.4 5952.1,5450 6185,5450 6265,5530 6265,5825 6241,5849 12V.1@6133.5,5849 6133.5,5841 v1(6109.3,5816.8) ; v1(6330,4900) 6341.3,4888.7 C32.2@6341.3,4868 6353.8,4855.5 U7.4@6353.8,4809.4
  Bottom Layer w5.5: v1(5700.7,5562.4) 5700.7,5552.4 5728,5525 6210,5525 6250,5565 6250,5790 6221.5,5818.5 v1@6111.9,5818.5 ; v1(5771.4,5369.2) 5771.4,5436.4 5786.4,5451.4 v1@5916.6,5451.4
  Bottom Layer w10: v1(6180,5450) 6265,5365 6265,4965 v1(6330,4900)
  other v1: 5918,5448.6
$1N181: C8.1 U1.1 | length 51.9
  Top Layer w10: U1.1@5859.5,5940 5862.4,5937 C8.1@5910.1,5937
$1N182: R6.2 U1.4 | length 50
  Top Layer w5.5: R6.2@5653.4,5922.7 U1.4@5703.4,5922.7
$1N183: C9.2 U1.6 | length 77.2
  Top Layer w5.5: U1.6@5759.5,5725.7 5759.5,5655.6 C9.2@5764.5,5650.6
$1N188: C8.2 D6.2 L1.1 U1.8 | length 250.6
  Top Layer w10: v1(5940,5900) 5965.2,5925.2 C8.2@5965.2,5937
  Bottom Layer w10: v1(5894.5,5715.7) 5940,5761.2 v1(5940,5900)
$1N190: C11.1 R19.1 R20.2 U1.5 | length 183.2
  Top Layer w5.5: R19.1@5641.6,5655.5 5645.9,5651.2 C11.1@5698.5,5651.2 5698.5,5686.3 U1.5@5708.3,5696.1 ; C11.1@5701.3,5650.2 5754.5,5596.9 R20.2@5754.8,5596.9
$1N195: C15.1 U2.6 | length 74.8
  Top Layer w10: U2.6@5736.8,5332.8 5736.8,5297.5 C15.1@5764.7,5269.6
$1N197: C15.2 L2.1 U2.2 | length 151.8
  Bottom Layer w10: v1(5819.8,5269.6) 5859.6,5269.6 5880,5290 5880,5372.9 v1(5879.9,5373.1)
  other v1: 6055,5395
$1N199: R21.1 R22.2 U2.4 | length 106.1
  Top Layer w5.5: R21.1@5632.8,5402.7 5634.9,5404.9 R22.2@5685,5404.9 5687.7,5407.6 U2.4@5736.8,5407.6
$1N212: LED2.2 R1.1 | length 70.9
  Top Layer w5.5: R1.1@6017.9,5100 6021.5,5096.4 LED2.2@6021.5,5030.6
$2N53: D16.1 Q1.4 R59.2 R84.2 | length 213.1
  Top Layer w10: Q1.4@7187.9,4281.4 7248.1,4281.4 R59.2@7261.8,4267.8 R84.2@7323.5,4267.8 7376.8,4267.8 D16.1@7390,4280.9
$2N376: D5.1 Q3.4 R11.2 R12.2 | length 213.1
  Top Layer w10: Q3.4@6502.9,4281.4 6563.1,4281.4 R11.2@6576.8,4267.8 R12.2@6638.5,4267.8 6691.8,4267.8 D5.1@6705,4280.9
$2N378: D12.1 Q5.4 R26.2 R27.2 | length 213.1
  Top Layer w10: Q5.4@5817.9,4281.4 5878.1,4281.4 R26.2@5891.8,4267.8 R27.2@5953.5,4267.8 6006.8,4267.8 D12.1@6020,4280.9
$2N380: D13.1 Q7.4 R28.2 R32.2 | length 204.9
  Top Layer w10: D13.1@6760,4045.9 6767.8,4038.1 R32.2@6827.1,4038.1 6837.4,4048.4 R28.2@6891.8,4048.4 6949.9,4048.4 Q7.4@6955.2,4053.7
$2N383: D14.1 Q8.4 R33.2 R34.2 | length 204.9
  Top Layer w10: D14.1@6075,4045.9 6082.8,4038.1 R34.2@6142.1,4038.1 6152.4,4048.4 R33.2@6206.8,4048.4 6264.9,4048.4 Q8.4@6270.2,4053.7
$2N386: D15.1 Q9.4 R35.2 R36.2 | length 204.9
  Top Layer w10: D15.1@5390,4045.9 5397.8,4038.1 R36.2@5457.1,4038.1 5467.4,4048.4 R35.2@5521.8,4048.4 5579.9,4048.4 Q9.4@5585.2,4053.7
$3N117: CN12.1 R25.2 U18.7 | length 465.3
  Top Layer w5.5: U18.7@7021.3,5947 6993,5947 6970,5970 6970,6015 CN12.1@7160,6205
  Top Layer w10: U18.7@7021.3,5947 7070.1,5947 R25.2@7099.8,5917.4
$3N118: CN12.2 R29.1 U18.6 | length 472.3
  Top Layer w5.5: CN12.2@7010,6205 6955,6150 6955,5935 6993,5897 U18.6@7021.3,5897
  Top Layer w10: U18.6@7021.3,5897 7055.1,5897 R29.1@7100.1,5852
$3N119: C28.2 R25.1 R29.2 | length 136.1
  Top Layer w10: C28.2@7156.3,5986.8 7159.1,5984 R25.1@7159.1,5917.4 7159.4,5917 R29.2@7159.4,5852
ADC_AI: U3.18 U10.8 | length 773.8
  Top Layer w5.5: U3.18@6662.2,5083.1 6662.2,5122.2 6675,5135 6935,5135 7219.8,4850.2 U10.8@7273.6,4850.2
ADC_AU: C21.2 D3.1 R58.1 R65.2 U3.20 | length 685.6
  Top Layer w5.5: U3.20@6701.5,5083.1 6701.5,5006 C21.2@6710,4997.6 6716.4,4997.6 v1(6744.6,4969.3) ; v1(7043.3,4776.7) 7055.9,4764.1 D3.1@7070,4764.1 7071.7,4762.3 R65.2@7143.7,4762.3 7208,4762.3 R58.1@7208.7,4763
  Bottom Layer w5.5: v1(6744.6,4969.3) 6838.9,4875 6945,4875 v1(7043.3,4776.7)
ADC_BI: U3.13 U6.8 | length 424.6
  Top Layer w5.5: U3.13@6565.7,5218.9 6566.8,5220 6605,5220 6615,5210 6615,5140 6596.5,5121.5 6596.5,4857.9 U6.8@6588.8,4850.2
ADC_BU: C61.2 D8.1 R66.1 R67.2 U3.19 | length 605.5
  Top Layer w5.5: C61.2@6630,5002.6 6681.8,5054.4 U3.19@6681.8,5083.1 ; C61.2@6640,4997.6 6675,4962.6 6675,4915 6700,4890 6770,4890 6790,4870 6790,4804.1 D8.1@6835,4759.1 6841.7,4765.8 R67.2@6910.2,4765.8 6974.6,4765.8 R66.1@6975.2,4766.5
ADC_CI: U3.14 U5.8 | length 835
  Top Layer w5.5: U5.8@5903.5,4850.2 5903.5,4898.5 5915,4910 6090,4910 6355,5175 6440,5175 6453.5,5188.5 6506.8,5188.5 6517.6,5199.2 U3.14@6565.7,5199.2
ADC_CU: C63.2 D9.1 R68.1 R69.2 U3.17 | length 1139.9
  Top Layer w5.5: D9.1@5678.7,4805.9 5695,4789.6 R69.2@5753.7,4789.6 R68.1@5818.7,4789.6 5890.4,4789.6 5900,4780 5970,4780 6015,4825 6115,4825 6285.6,4995.6 6568,4995.6 C63.2@6570,4997.6 v1(6570,5040) ; v1(6625,5040) 6642.5,5057.5 U3.17@6642.5,5083.1
  Bottom Layer w5.5: v1(6570,5040) v1(6625,5040)
ADC_U: C64.2 D1.1 R70.1 R71.2 U3.12 | length 1279.2
  Top Layer w5.5: R71.2@5675,4739.7 R70.1@5600,4739.7 5605,4744.7 D1.1@5605,4799.1 5645.9,4840 5810,4840 5935,4965 6080,4965 6320,5205 C64.2@6417.6,5205 6500,5205 6533.6,5238.6 U3.12@6565.7,5238.6
AGND: C2.2 C5.2 C6.1 C7.2 C9.1 C10.1 C12.1 C13.1 C14.1 C16.1 C17.1 C18.2 C19.2 C20.1 C21.1 C22.1 C23.1 C24.1 C25.1 C26.2 C27.1 C28.1 C32.1 C33.2 C34.2 C35.2 C36.2 C37.2 C38.2 C39.1 C40.1 C41.1 C61.1 C63.1 C64.1 C67.1 CN3.1 CN4.2 CN5.2 D2.1 D6.1 D10.1 H1.3 H4.2 LED2.1 OLED2.1 PGND.1 Q7.1 Q7.2 Q7.3 Q8.1 Q8.2 Q8.3 Q9.1 Q9.2 Q9.3 R6.1 R20.1 R22.1 R28.1 R33.1 R35.1 R65.1 R67.1 R69.1 R71.1 SCREW2.1 SCREW3.1 SCREW4.1 SW1.1 U1.7 U1.9 U2.1 U3.15 U3.27 U3.31 U3.47 U3.63 U4.2 U5.4 U5.7 U6.4 U6.7 U7.6 U7.25 U9.2 U10.4 U10.7 U18.2 U18.8 X1.2 X1.4 | length 779.6
  Top Layer w5.5: v1(5685,5313.9) R22.1@5685,5345.6
  Top Layer w10: R35.1@5521.8,4107.8 5581.1,4107.8 Q9.3@5585.2,4103.7 ; v1(5765,5115) 5785,5095 C17.1@5785,5087.6 ; C41.1@6045,4797.4 6058,4797.4 v1(6072.9,4782.5) ; D2.1@6107,6175 6157.9,6124.2 PGND.1@6157.9,6108.3 ; R33.1@6206.8,4107.8 6266.1,4107.8 Q8.3@6270.2,4103.7 ; C32.1@6286.2,4868 6314.4,4839.7 U7.6@6314.4,4809.4 ; R28.1@6891.8,4107.8 6951.1,4107.8 Q7.3@6955.2,4103.7
  Bottom Layer w5.5: v1(5685,5313.9) 5685,5311.4 5762.8,5233.5 5868.6,5233.5 v1(5943.8,5308.7)
  other v1: 5204.1,3644.1 5404.1,3644.1 5604.1,3644.1 5804.1,3644.1 6004.1,3644.1 7204.1,3644.1 7404.1,3644.1 5204.1,3844.1 5404.1,3844.1 5604.1,3844.1 5804.1,3844.1 6404.1,3844.1 6804.1,3844.1 7404.1,3844.1 5204.1,4044.1 6004.1,4044.1 7404.1,4044.1 5562.9,4103.7 6247.9,4103.7 6932.9,4103.7 5527.9,4138.7 5562.9,4138.7 5597.9,4138.7 6212.9,4138.7 6247.9,4138.7 6282.9,4138.7 6897.9,4138.7 6932.9,4138.7 6967.9,4138.7 5492.9,4173.7 5527.9,4173.7 5562.9,4173.7 6177.9,4173.7 6212.9,4173.7 6247.9,4173.7 6862.9,4173.7 6897.9,4173.7 6932.9,4173.7 5492.9,4208.7 5527.9,4208.7 5562.9,4208.7 5597.9,4208.7 6177.9,4208.7 6212.9,4208.7 6247.9,4208.7 6282.9,4208.7 6862.9,4208.7 6897.9,4208.7 6932.9,4208.7 6967.9,4208.7 5204.1,4244.1 5492.9,4243.7 5527.9,4243.7 5562.9,4243.7 5597.9,4243.7 6004.1,4244.1 6177.9,4243.7 6212.9,4243.7 6247.9,4243.7 6282.9,4243.7 6804.1,4244.1 6862.9,4243.7 6897.9,4243.7 6932.9,4243.7 6967.9,4243.7 5527.9,4278.7 5562.9,4278.7 5597.9,4278.7 6212.9,4278.7 6247.9,4278.7 6282.9,4278.7 6897.9,4278.7 6932.9,4278.7 6967.9,4278.7 6190,4580 6805,4585 7135,4595 7367,4595 5510,4600 7490,4600 5820,4605 6005,4605 6965,4605 5027.5,4620 5062.5,4620 6690,4620 5804.1,4644.1 6004.1,4644.1 7204.1,4644.1 7404.1,4644.1 5027.5,4655 5062.5,4655 6195,4665 5027.5,4690 5062.5,4690 6335,4705 6391.3,4705 5875,4720 6040,4725 6363.6,4734.6 6510,4755 6335,4765 6389.4,4765 7440,4775 6758.2,4782.5 6845,4800 5930,4805 6615.3,4805 7300.1,4805 6445,4825 5604.1,4844.1 6204.1,4844.1 6005,4885 6115,4885 6262.6,4892.3 5770,4895 7500,4905 6624.2,4915.3 6725.7,4915.3 5955,4935 7510,4955 6542,4959 6429.8,4960.2 6917.5,4961.9 6792.5,4967.1 6325,4970 5204.1,5044.1 5604.1,5044.1 6404.1,5044.1 7204.1,5044.1 7404.1,5044.1 5988.1,5058.1 6970,5060 6617.2,5075 6567.2,5097.8 6073,5109.2 7050,5125 7235,5130 6970,5135 5905,5150 6460.5,5152.5 6865,5160 6315,5170 5980,5173 6450,5235 5204.1,5244.1 5604.1,5244.1 6204.1,5244.1 6500,5250 6615,5250 7065,5285 6505,5290 6360,5300 7255,5300 7385,5300 5790,5319.8 6515,5325 6955,5340 5945,5350 6350,5350 6665,5355 7503.3,5401.2 6345,5405 6150,5420 6518.6,5420.3 7105,5439.2 5604.1,5444.1 6520,5465 6345,5470 6800,5470 6673.3,5470.9 6970,5480 6275,5495 6505,5510 6360,5535 6405,5570 6455,5570 6865.9,5590 7510,5625 5204.1,5644.1 5604.1,5644.1 6404.1,5644.1 6670.1,5653.5 6300,5655 6582.9,5656 6975,5700 7225,5700 7110,5749.3 6940,5795 6180,5797.8 7020,5815 6000,5840 5204.1,5844.1 5604.1,5844.1 6404.1,5844.1 6750,5850 6960,5870 6649.3,5880 6712,5962.5 5675,5965 7515,5970 7115,6010 6082.5,6015 6117.5,6015 5204.1,6044.1 6004.1,6044.1 6204.1,6044.1 6404.1,6044.1 7404.1,6044.1 6082.5,6050 6117.5,6050 6082.5,6085 6117.5,6085 6995,6090 5467.5,6145 5502.5,6145 5467.5,6180 5502.5,6180 5467.5,6215 5502.5,6215 5204.1,6244.1 5404.1,6244.1 5604.1,6244.1 6204.1,6244.1 7404.1,6244.1 5695,6250 5985,6250
BSTA: C29.2 U7.20 | length 58.1
  Top Layer w10: U7.20@6438.4,4705.1 6485.5,4705.1 C29.2@6493.3,4712.9
BSTB: C30.1 U7.17 | length 63.5
  Top Layer w10: U7.17@6393.1,4659.8 6393.1,4610.6 C30.1@6403.2,4600.5
BSTC: C31.1 U7.14 | length 88
  Top Layer w10: C31.1@6283.4,4600.5 6296.5,4600.5 6334.1,4638.1 U7.14@6334.1,4659.8
DCBUS: 24V.1 C2.1 C5.1 C7.1 C13.2 C33.1 C34.1 C35.1 C36.1 C37.1 C38.1 D2.2 D10.2 Q1.5 Q1.6 Q1.7 Q1.8 Q3.5 Q3.6 Q3.7 Q3.8 Q5.5 Q5.6 Q5.7 Q5.8 R70.2 U1.2 U1.3 U9.1 | length 147.2
  Top Layer w5.5: 5455,4675 5594.7,4675 R70.2@5600,4680.3
FDCAN1_RX: U3.45 U18.4 | length 947.2
  Top Layer w5.5: U18.4@6808.3,5847 6885.3,5770 7159.3,5770 v1(7170,5759.3) ; v1(6901.1,5466.5) 6971.5,5396.1 U3.45@7013.6,5396.1
  Bottom Layer w5.5: v1(6901.1,5466.5) 6901.1,5496.1 7164.3,5759.3 v1(7170,5759.3)
FDCAN1_TX: U3.46 U18.1 | length 1087.7
  Top Layer w5.5: U18.1@6808.3,5997 6810.3,5995 6870,5995 6905,5960 6905,5880 6995,5790 v1(7220,5790) ; v1(6930,5480) 6930,5474.7 6988.9,5415.8 U3.46@7013.6,5415.8
  Bottom Layer w5.5: v1(6930,5480) 6930,5485 7220,5775 v1(7220,5790)
GHA: D16.2 R84.1 U7.19 | length 1469.9
  Top Layer w10: U7.19@6438.4,4685.4 v1(6529.1,4685.4) ; R84.1@7323.5,4208.4 7380.6,4208.4 D16.2@7390,4199.1 v1(7390,4240)
  PWR03 w10: v1(6529.1,4685.4) 6529.5,4685 7325,4685 7390,4620 v1(7390,4240)
GHB: D5.2 R12.1 U7.16 | length 937.2
  Top Layer w10: U7.16@6373.5,4659.8 6373.5,4634.1 6374.9,4632.7 6374.9,4565 v1(6375,4564.8) ; R12.1@6638.5,4208.4 6695.6,4208.4 D5.2@6705,4199.1 6741.1,4235.1 v1(6741.1,4309.2)
  PWR03 w10: v1(6375,4564.8) 6405.2,4595 6710,4595 6741.1,4563.9 v1(6741.1,4309.2)
GHC: D12.2 R27.1 U7.13 | length 763.4
  Top Layer w10: R27.1@5953.5,4208.4 6010.6,4208.4 D12.2@6018.9,4200.2 ; D12.2@6020,4199.1 D12.2@6018.9,4200.2 ; v1(6053.9,4309.3) 6053.9,4235.2 D12.2@6018.9,4200.2 ; v1(6284.1,4643.1) 6300.8,4659.8 U7.13@6314.4,4659.8
  PWR03 w10: v1(6053.9,4309.3) 6053.9,4588.9 6105,4640 6281,4640 v1(6284.1,4643.1)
